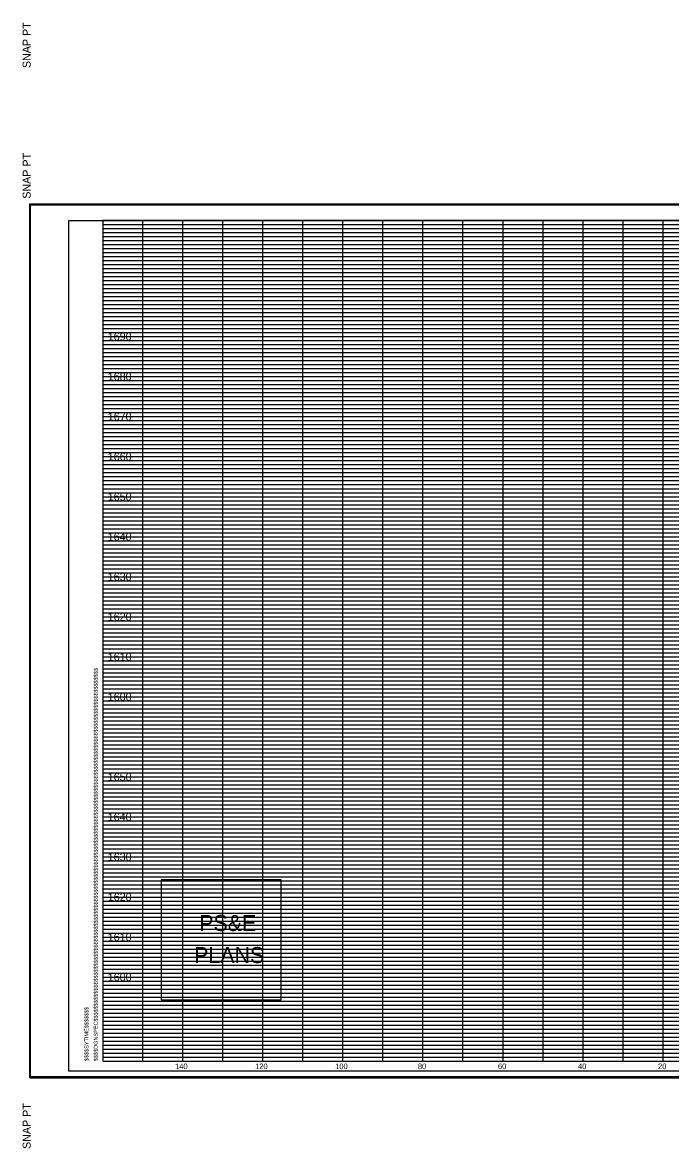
# Model space of a CAD drawing. Extents: x 980 to 1324, y 978 to 1767.
# Drawn here: x 979.9 to 1141.8, y 978.2 to 1259.4 of the extents above; entities that cross this region are included whole.
import ezdxf

# ---------------------------------------------------------------- set-up
doc = ezdxf.new("R2010")
doc.units = 0
for name, color, linetype in [('DESIGN - SHEET - Corner Text', 7, 'Continuous'), ('DESIGN - SHEET - Light Grid', 7, 'Continuous'), ('DESIGN - SHEET - Linework', 7, 'Continuous'), ('DESIGN - SHEET - Plot Shape', 7, 'Continuous'), ('DESIGN - TYPICAL - Finished Grade and Subgrade', 7, 'Continuous')]:
    doc.layers.add(name, color=color, linetype=linetype)

# ---------------------------------------------------------------- blocks, each defined once
blk = doc.blocks.new('XSTSHT')
at = {"layer": 'DESIGN - SHEET - Light Grid'}
for p, q in [((0, 20.9), (8, 20.9)), ((8, 20.9), (16, 20.9)), ((0, 20.8), (8, 20.8)), ((0, 20.7), (8, 20.7)), ((0, 20.6), (8, 20.6)), ((8, 20.8), (16, 20.8)), ((8, 20.7), (16, 20.7)), ((8, 20.6), (16, 20.6)), ((0, 20.5), (8, 20.5)), ((0, 20.4), (8, 20.4)), ((0, 20.3), (8, 20.3)), ((8, 20.5), (16, 20.5)), ((8, 20.4), (16, 20.4)), ((8, 20.3), (16, 20.3)), ((0, 20.2), (8, 20.2)), ((0, 20.1), (8, 20.1)), ((8, 20.2), (16, 20.2)), ((8, 20.1), (16, 20.1)), ((0, 19.9), (8, 19.9)), ((0, 19.8), (8, 19.8)), ((0, 19.7), (8, 19.7)), ((8, 19.9), (16, 19.9)), ((8, 19.8), (16, 19.8)), ((8, 19.7), (16, 19.7)), ((0, 19.6), (8, 19.6)), ((0, 19.5), (8, 19.5)), ((8, 19.6), (16, 19.6)), ((8, 19.5), (16, 19.5)), ((0, 19.4), (8, 19.4)), ((0, 19.3), (8, 19.3)), ((0, 19.2), (8, 19.2)), ((8, 19.4), (16, 19.4)), ((8, 19.3), (16, 19.3)), ((8, 19.2), (16, 19.2)), ((0, 19.1), (8, 19.1)), ((0, 18.9), (8, 18.9)), ((8, 19.1), (16, 19.1)), ((8, 18.9), (16, 18.9)), ((0, 18.8), (8, 18.8)), ((0, 18.7), (8, 18.7)), ((0, 18.6), (8, 18.6)), ((8, 18.8), (16, 18.8)), ((8, 18.7), (16, 18.7)), ((8, 18.6), (16, 18.6)), ((0, 18.5), (8, 18.5)), ((0, 18.4), (8, 18.4)), ((0, 18.3), (8, 18.3)), ((8, 18.5), (16, 18.5)), ((8, 18.4), (16, 18.4)), ((8, 18.3), (16, 18.3)), ((0, 18.2), (8, 18.2)), ((0, 18.1), (8, 18.1)), ((8, 18.2), (16, 18.2)), ((8, 18.1), (16, 18.1)), ((0, 17.9), (8, 17.9)), ((0, 17.8), (8, 17.8)), ((8, 17.9), (16, 17.9)), ((8, 17.8), (16, 17.8)), ((0, 17.7), (8, 17.7)), ((0, 17.6), (8, 17.6)), ((0, 17.5), (8, 17.5)), ((8, 17.7), (16, 17.7)), ((8, 17.6), (16, 17.6)), ((8, 17.5), (16, 17.5)), ((0, 17.4), (8, 17.4)), ((0, 17.3), (8, 17.3)), ((0, 17.2), (8, 17.2)), ((8, 17.4), (16, 17.4)), ((8, 17.3), (16, 17.3)), ((8, 17.2), (16, 17.2)), ((0, 17.1), (8, 17.1)), ((0, 16.9), (8, 16.9)), ((8, 17.1), (16, 17.1)), ((8, 16.9), (16, 16.9)), ((0, 16.8), (8, 16.8)), ((0, 16.7), (8, 16.7)), ((0, 16.6), (8, 16.6)), ((8, 16.8), (16, 16.8)), ((8, 16.7), (16, 16.7)), ((8, 16.6), (16, 16.6)), ((0, 16.5), (8, 16.5)), ((0, 16.4), (8, 16.4)), ((8, 16.5), (16, 16.5)), ((8, 16.4), (16, 16.4)), ((0, 16.3), (8, 16.3)), ((0, 16.2), (8, 16.2)), ((0, 16.1), (8, 16.1)), ((8, 16.3), (16, 16.3)), ((8, 16.2), (16, 16.2)), ((8, 16.1), (16, 16.1)), ((0, 15.9), (8, 15.9)), ((0, 15.8), (8, 15.8)), ((8, 15.9), (16, 15.9)), ((8, 15.8), (16, 15.8)), ((0, 15.7), (8, 15.7)), ((0, 15.6), (8, 15.6)), ((0, 15.5), (8, 15.5)), ((8, 15.7), (16, 15.7)), ((8, 15.6), (16, 15.6)), ((8, 15.5), (16, 15.5)), ((0, 15.4), (8, 15.4)), ((0, 15.3), (8, 15.3)), ((0, 15.2), (8, 15.2)), ((8, 15.4), (16, 15.4)), ((8, 15.3), (16, 15.3)), ((8, 15.2), (16, 15.2)), ((0, 15.1), (8, 15.1)), ((8, 15.1), (16, 15.1)), ((0, 14.9), (8, 14.9)), ((0, 14.8), (8, 14.8)), ((0, 14.7), (8, 14.7)), ((8, 14.9), (16, 14.9)), ((8, 14.8), (16, 14.8)), ((8, 14.7), (16, 14.7)), ((0, 14.6), (8, 14.6)), ((0, 14.5), (8, 14.5)), ((0, 14.4), (8, 14.4)), ((8, 14.6), (16, 14.6)), ((8, 14.5), (16, 14.5)), ((8, 14.4), (16, 14.4)), ((0, 14.3), (8, 14.3)), ((0, 14.2), (8, 14.2)), ((0, 14.1), (8, 14.1)), ((8, 14.3), (16, 14.3)), ((8, 14.2), (16, 14.2)), ((8, 14.1), (16, 14.1)), ((0, 13.9), (8, 13.9)), ((0, 13.8), (8, 13.8)), ((8, 13.9), (16, 13.9)), ((8, 13.8), (16, 13.8)), ((0, 13.7), (8, 13.7)), ((0, 13.6), (8, 13.6)), ((8, 13.7), (16, 13.7)), ((8, 13.6), (16, 13.6)), ((0, 13.5), (8, 13.5)), ((0, 13.4), (8, 13.4)), ((0, 13.3), (8, 13.3)), ((8, 13.5), (16, 13.5)), ((8, 13.4), (16, 13.4)), ((8, 13.3), (16, 13.3)), ((0, 13.2), (8, 13.2)), ((0, 13.1), (8, 13.1)), ((8, 13.2), (16, 13.2)), ((8, 13.1), (16, 13.1)), ((0, 12.9), (8, 12.9)), ((0, 12.8), (8, 12.8)), ((0, 12.7), (8, 12.7)), ((8, 12.9), (16, 12.9)), ((8, 12.8), (16, 12.8)), ((8, 12.7), (16, 12.7)), ((0, 12.6), (8, 12.6)), ((0, 12.5), (8, 12.5)), ((0, 12.4), (8, 12.4)), ((8, 12.6), (16, 12.6)), ((8, 12.5), (16, 12.5)), ((8, 12.4), (16, 12.4)), ((0, 12.3), (8, 12.3)), ((0, 12.2), (8, 12.2)), ((0, 12.1), (8, 12.1)), ((8, 12.3), (16, 12.3)), ((8, 12.2), (16, 12.2)), ((8, 12.1), (16, 12.1)), ((0, 11.9), (8, 11.9)), ((8, 11.9), (16, 11.9)), ((0, 11.8), (8, 11.8)), ((0, 11.7), (8, 11.7)), ((0, 11.6), (8, 11.6)), ((8, 11.8), (16, 11.8)), ((8, 11.7), (16, 11.7)), ((8, 11.6), (16, 11.6)), ((0, 11.5), (8, 11.5)), ((0, 11.4), (8, 11.4)), ((0, 11.3), (8, 11.3)), ((8, 11.5), (16, 11.5)), ((8, 11.4), (16, 11.4)), ((8, 11.3), (16, 11.3)), ((0, 11.2), (8, 11.2)), ((0, 11.1), (8, 11.1)), ((8, 11.2), (16, 11.2)), ((8, 11.1), (16, 11.1)), ((0, 10.9), (8, 10.9)), ((0, 10.8), (8, 10.8)), ((0, 10.7), (8, 10.7)), ((8, 10.9), (16, 10.9)), ((8, 10.8), (16, 10.8)), ((8, 10.7), (16, 10.7)), ((0, 10.6), (8, 10.6)), ((0, 10.5), (8, 10.5)), ((8, 10.6), (16, 10.6)), ((8, 10.5), (16, 10.5)), ((0, 10.4), (8, 10.4)), ((0, 10.3), (8, 10.3)), ((0, 10.2), (8, 10.2)), ((8, 10.4), (16, 10.4)), ((8, 10.3), (16, 10.3)), ((8, 10.2), (16, 10.2)), ((0, 10.1), (8, 10.1)), ((0, 9.9), (8, 9.9)), ((8, 10.1), (16, 10.1)), ((8, 9.9), (16, 9.9)), ((0, 9.8), (8, 9.8)), ((0, 9.7), (8, 9.7)), ((0, 9.6), (8, 9.6)), ((8, 9.8), (16, 9.8)), ((8, 9.7), (16, 9.7)), ((8, 9.6), (16, 9.6)), ((0, 9.5), (8, 9.5)), ((0, 9.4), (8, 9.4)), ((0, 9.3), (8, 9.3)), ((8, 9.5), (16, 9.5)), ((8, 9.4), (16, 9.4)), ((8, 9.3), (16, 9.3)), ((0, 9.2), (8, 9.2)), ((0, 9.1), (8, 9.1)), ((8, 9.2), (16, 9.2)), ((8, 9.1), (16, 9.1)), ((0, 8.9), (8, 8.9)), ((0, 8.8), (8, 8.8)), ((8, 8.9), (16, 8.9)), ((8, 8.8), (16, 8.8)), ((0, 8.7), (8, 8.7)), ((0, 8.6), (8, 8.6)), ((0, 8.5), (8, 8.5)), ((8, 8.7), (16, 8.7)), ((8, 8.6), (16, 8.6)), ((8, 8.5), (16, 8.5)), ((0, 8.4), (8, 8.4)), ((0, 8.3), (8, 8.3)), ((0, 8.2), (8, 8.2)), ((8, 8.4), (16, 8.4)), ((8, 8.3), (16, 8.3)), ((8, 8.2), (16, 8.2)), ((0, 8.1), (8, 8.1)), ((0, 7.9), (8, 7.9)), ((8, 8.1), (16, 8.1)), ((8, 7.9), (16, 7.9)), ((0, 7.8), (8, 7.8)), ((0, 7.7), (8, 7.7)), ((0, 7.6), (8, 7.6)), ((8, 7.8), (16, 7.8)), ((8, 7.7), (16, 7.7)), ((8, 7.6), (16, 7.6)), ((0, 7.5), (8, 7.5)), ((0, 7.4), (8, 7.4)), ((8, 7.5), (16, 7.5)), ((8, 7.4), (16, 7.4)), ((0, 7.3), (8, 7.3)), ((0, 7.2), (8, 7.2)), ((0, 7.1), (8, 7.1)), ((8, 7.3), (16, 7.3)), ((8, 7.2), (16, 7.2)), ((8, 7.1), (16, 7.1)), ((0, 6.9), (8, 6.9)), ((0, 6.8), (8, 6.8)), ((8, 6.9), (16, 6.9)), ((8, 6.8), (16, 6.8)), ((0, 6.7), (8, 6.7)), ((0, 6.6), (8, 6.6)), ((0, 6.5), (8, 6.5)), ((8, 6.7), (16, 6.7)), ((8, 6.6), (16, 6.6)), ((8, 6.5), (16, 6.5)), ((0, 6.4), (8, 6.4)), ((0, 6.3), (8, 6.3)), ((0, 6.2), (8, 6.2)), ((8, 6.4), (16, 6.4)), ((8, 6.3), (16, 6.3)), ((8, 6.2), (16, 6.2)), ((0, 6.1), (8, 6.1)), ((8, 6.1), (16, 6.1)), ((0, 5.9), (8, 5.9)), ((0, 5.8), (8, 5.8)), ((0, 5.7), (8, 5.7)), ((8, 5.9), (16, 5.9)), ((8, 5.8), (16, 5.8)), ((8, 5.7), (16, 5.7)), ((0, 5.6), (8, 5.6)), ((0, 5.5), (8, 5.5)), ((0, 5.4), (8, 5.4)), ((8, 5.6), (16, 5.6)), ((8, 5.5), (16, 5.5)), ((8, 5.4), (16, 5.4)), ((0, 5.3), (8, 5.3)), ((0, 5.2), (8, 5.2)), ((0, 5.1), (8, 5.1)), ((8, 5.3), (16, 5.3)), ((8, 5.2), (16, 5.2)), ((8, 5.1), (16, 5.1)), ((0, 4.9), (8, 4.9)), ((0, 4.8), (8, 4.8)), ((8, 4.9), (16, 4.9)), ((8, 4.8), (16, 4.8)), ((0, 4.7), (8, 4.7)), ((0, 4.6), (8, 4.6)), ((8, 4.7), (16, 4.7)), ((8, 4.6), (16, 4.6)), ((0, 4.5), (8, 4.5)), ((0, 4.4), (8, 4.4)), ((0, 4.3), (8, 4.3)), ((8, 4.5), (16, 4.5)), ((8, 4.4), (16, 4.4)), ((8, 4.3), (16, 4.3)), ((0, 4.2), (8, 4.2)), ((0, 4.1), (8, 4.1)), ((8, 4.2), (16, 4.2)), ((8, 4.1), (16, 4.1)), ((0, 3.9), (8, 3.9)), ((0, 3.8), (8, 3.8)), ((0, 3.7), (8, 3.7)), ((8, 3.9), (16, 3.9)), ((8, 3.8), (16, 3.8)), ((8, 3.7), (16, 3.7)), ((0, 3.6), (8, 3.6)), ((0, 3.5), (8, 3.5)), ((0, 3.4), (8, 3.4)), ((8, 3.6), (16, 3.6)), ((8, 3.5), (16, 3.5)), ((8, 3.4), (16, 3.4)), ((0, 3.3), (8, 3.3)), ((0, 3.2), (8, 3.2)), ((0, 3.1), (8, 3.1)), ((8, 3.3), (16, 3.3)), ((8, 3.2), (16, 3.2)), ((8, 3.1), (16, 3.1)), ((0, 2.9), (8, 2.9)), ((8, 2.9), (16, 2.9)), ((0, 2.8), (8, 2.8)), ((0, 2.7), (8, 2.7)), ((0, 2.6), (8, 2.6)), ((8, 2.8), (16, 2.8)), ((8, 2.7), (16, 2.7)), ((8, 2.6), (16, 2.6)), ((0, 2.5), (8, 2.5)), ((0, 2.4), (8, 2.4)), ((0, 2.3), (8, 2.3)), ((8, 2.5), (16, 2.5)), ((8, 2.4), (16, 2.4)), ((8, 2.3), (16, 2.3)), ((0, 2.2), (8, 2.2)), ((0, 2.1), (8, 2.1)), ((8, 2.2), (16, 2.2)), ((8, 2.1), (16, 2.1)), ((0, 1.9), (8, 1.9)), ((0, 1.8), (8, 1.8)), ((0, 1.7), (8, 1.7)), ((8, 1.9), (16, 1.9)), ((8, 1.8), (16, 1.8)), ((8, 1.7), (16, 1.7)), ((0, 1.6), (8, 1.6)), ((0, 1.5), (8, 1.5)), ((8, 1.6), (16, 1.6)), ((8, 1.5), (16, 1.5)), ((0, 1.4), (8, 1.4)), ((0, 1.3), (8, 1.3)), ((0, 1.2), (8, 1.2)), ((8, 1.4), (16, 1.4)), ((8, 1.3), (16, 1.3)), ((8, 1.2), (16, 1.2)), ((0, 1.1), (8, 1.1)), ((0, 0.9), (8, 0.9)), ((8, 1.1), (16, 1.1)), ((8, 0.9), (16, 0.9)), ((0, 0.8), (8, 0.8)), ((0, 0.7), (8, 0.7)), ((0, 0.6), (8, 0.6)), ((8, 0.8), (16, 0.8)), ((8, 0.7), (16, 0.7)), ((8, 0.6), (16, 0.6)), ((0, 0.5), (8, 0.5)), ((0, 0.4), (8, 0.4)), ((0, 0.3), (8, 0.3)), ((8, 0.5), (16, 0.5)), ((8, 0.4), (16, 0.4)), ((8, 0.3), (16, 0.3)), ((0, 0.2), (8, 0.2)), ((0, 0.1), (8, 0.1)), ((8, 0.2), (16, 0.2)), ((8, 0.1), (16, 0.1))]:
    blk.add_line(p, q, dxfattribs=at)
at = {"layer": 'DESIGN - SHEET - Linework'}
for p, q in [((-1.823, -0.414), (-1.823, 21.414)), ((-1.823, 21.414), (32.217, 21.414)), ((1, 0), (1, 21)), ((2, 0), (2, 21)), ((3, 0), (3, 21)), ((4, 0), (4, 21)), ((5, 0), (5, 21)), ((6, 0), (6, 21)), ((7, 0), (7, 21)), ((8, 0), (8, 21)), ((9, 0), (9, 21)), ((10, 0), (10, 21)), ((11, 0), (11, 21)), ((12, 0), (12, 21)), ((13, 0), (13, 21)), ((14, 0), (14, 21)), ((0, 20), (28, 20)), ((0, 19), (32, 19)), ((0, 18), (32, 18)), ((0, 17), (32, 17)), ((0, 16), (32, 16)), ((0, 15), (32, 15)), ((0, 14), (32, 14)), ((0, 13), (32, 13)), ((0, 12), (32, 12)), ((0, 11), (32, 11)), ((0, 10), (32, 10)), ((0, 9), (32, 9)), ((0, 8), (32, 8)), ((0, 7), (32, 7)), ((0, 6), (32, 6)), ((0, 5), (32, 5)), ((0, 4), (32, 4)), ((0, 3), (32, 3)), ((0, 2), (32, 2)), ((0, 1), (32, 1)), ((-1.823, -0.414), (32.217, -0.414))]:
    blk.add_line(p, q, dxfattribs=at)
blk.add_lwpolyline([(0, 21), (0, 0), (32, 0), (32, 21), (0, 21)], dxfattribs=at)
at = {"layer": 'DESIGN - SHEET - Plot Shape'}
for points in [[(-1.803, 21.394), (32.197, 21.394), (32.197, -0.394), (-1.803, -0.394)], [(-0.85, 21), (32, 21), (32, -0.25), (-0.85, -0.25)]]:
    blk.add_lwpolyline(points, close=True, dxfattribs=at)
at = {"layer": 'DESIGN - SHEET - Corner Text'}
for s, height, p in [('  SNAP PT', 0.2, (-1.803, 21.394)), ('$$$$DGNSPEC$$$$$$$$$$$$$$$$$$$$$$$$$$$$$$$$$$$$$$$$$$$$$$$$$$$$$$$$$$$$$$$$$$$$$$$$$$$$$$$$$$$$$$$$$$$$$$$$$$$$$$$$$$$$$$$$$$$', 0.100002, (-0.126, 0)), ('$$$$SYTIME$$$$$$$', 0.1, (-0.358, 0)), ('SNAP PT  ', 0.2, (-1.803, -2.194))]:
    blk.add_text(s, height=height, rotation=90, dxfattribs=at).set_placement(p)

msp = doc.modelspace()

# ---------------------------------------------------------------- linework, layer by layer
at = {"layer": 'DESIGN - SHEET - Corner Text'}
msp.add_lwpolyline([(1014.57, 1045.32), (1014.57, 1015.32), (1044.57, 1015.32), (1044.57, 1045.32)], close=True, dxfattribs=at)
at = {"layer": 'DESIGN - SHEET - Plot Shape'}
msp.add_lwpolyline([(991.5, 1210), (1320, 1210), (1320, 997.5), (991.5, 997.5)], close=True, dxfattribs=at)

# ---------------------------------------------------------------- block references
at = {"layer": 'DESIGN - TYPICAL - Finished Grade and Subgrade', "xscale": 10, "yscale": 10}
for p in [(1000, 1270), (1000, 1000)]:
    msp.add_blockref('XSTSHT', p, dxfattribs=at)

# ---------------------------------------------------------------- texts
at = {"layer": 'DESIGN - SHEET - Corner Text'}
for s, height, p in [('1690', 2, (1001.25, 1180)), ('1680', 2, (1001.25, 1170)), ('1670', 2, (1001.25, 1160)), ('1660', 2, (1001.25, 1150)), ('1650', 2, (1001.25, 1140)), ('1640', 2, (1001.25, 1130)), ('1630', 2, (1001.25, 1120)), ('1620', 2, (1001.25, 1110)), ('1610', 2, (1001.25, 1100)), ('1600', 2, (1001.25, 1090)), ('1650', 2, (1001.25, 1070)), ('1640', 2, (1001.25, 1060)), ('1630', 2, (1001.25, 1050)), ('1620', 2, (1001.25, 1040)), ('PS&E', 4, (1024.09, 1032.5)), ('1610', 2, (1001.25, 1030)), ('PLANS', 4, (1022.81, 1024.5)), ('1600', 2, (1001.25, 1020)), ('140', 1.4, (1018.06, 998)), ('120', 1.4, (1038.06, 998)), ('100', 1.4, (1058.06, 998)), ('80', 1.4, (1078.74, 998)), ('60', 1.4, (1098.74, 998)), ('40', 1.4, (1118.74, 998)), ('20', 1.4, (1138.74, 998))]:
    msp.add_text(s, height=height, dxfattribs=at).set_placement(p)

doc.saveas('drawing.dxf')
